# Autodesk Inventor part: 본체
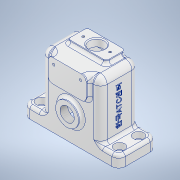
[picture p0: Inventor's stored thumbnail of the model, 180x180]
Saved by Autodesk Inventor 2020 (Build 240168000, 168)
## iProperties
Created: 2023-12
Part Number: 본체
Material: 알루미늄 6061
Document SubType Name: Modeling
Designer: oem
Density: 2.7 g/cm^3
Appearance: 알루미늄 - 평지
Mass: 227.593 g
Surface Area: 373.16 cm^2
Volume: 84.2938 cm^3
Author: oem
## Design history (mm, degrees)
sketch "스케치2"
  geometry: L1 (50, 20)-(-50, 20); L2 (-50, 20)-(-50, -20); L3 (-50, -20)-(50, -20); L4 (50, -20)-(50, 20); L5 (50, 20)-(-50, -20); L6 (-50, 20)-(50, -20); 1 further point
  constraints: 12 end point, 2 midpoint, 2 parallel, 1 horizontal, 1 perpendicular
  dimensions: "d0" = 100 distance of L2.end L3.end; "d1" = 40 distance of L3.end L1.start
extrude "돌출1" new body sketch "스케치2" distance "d2" = 12; taper "d3" = 0 deg
sketch "스케치3"
  geometry: L1 (-31, 72)-(31, 72); L2 (31, 72)-(31, 0); L3 (31, 0)-(-31, 0); L4 (-31, 0)-(-31, 72); L5 (50, 0)-(-50, 0) reference; 2 further points
  constraints: 8 end point, 2 parallel, 1 coincident, 1 horizontal, 1 midpoint, 1 perpendicular
  dimensions: "d4" = 62 distance of L1.start L1.end; "d5" = 72 distance between parallel lines of L5 L1
extrude "돌출2" join sketch "스케치3" stored distance "d6" = 40; taper "d7" = 0 deg
sketch "스케치4"
  geometry: L1 (0, 0)-(100, 0) reference; L2 (81, 72)-(19, 72) reference; L3 (30, 72)-(70, 72); L4 (70, 72)-(70, 48); L5 (70, 48)-(30, 48); L6 (30, 48)-(30, 72); C1 r 12 at (50, 28); 5 further points
  constraints: 8 end point, 3 midpoint, 2 parallel, 2 vertical alignment, 1 centre point, 1 horizontal, 1 perpendicular, 1 point on line
  dimensions: "d8" = 24 diameter of C1; "d9" = 28 distance of point (50, 0) C1.centre; "d10" = 40 distance between parallel lines of L4 L6; "d11" = 24 distance between parallel lines of L5 L2
extrude "돌출3" join sketch "스케치4" distance "d12" = 4; taper "d13" = 0 deg
sketch "스케치5"
  geometry: C1 r 12 at (50, 28) reference; C2 r 20 at (50, 28); 1 further point
  constraints: 1 centre point, 1 coincident
  dimensions: "d14" = 40 diameter of C2
extrude "돌출4" join sketch "스케치5" distance "d15" = 4; taper "d16" = 0 deg
sketch "스케치6"
  geometry: L1 (51, -44)-(11, -44) reference; L2 (11, -3)-(51, -3); L3 (51, -3)-(51, -23); L4 (51, -23)-(11, -23); L5 (11, -23)-(11, -3); L6 (11, -13)-(51, -13); 2 further points
  constraints: 10 end point, 3 midpoint, 2 parallel, 1 horizontal, 1 perpendicular, 1 vertical alignment
  dimensions: "d18" = 20 distance between parallel lines of L4 L2; "d19" = 40 distance of L2.start L2.end; "d20" = 31 distance between parallel lines of L1 L6
extrude "돌출5" join sketch "스케치6" distance "d21" = 4; taper "d22" = 0 deg
sketch "스케치7"
  geometry: C1 r 12 at (0, 0) reference; 2 further points
  constraints: 1 coincident
hole "구멍1" sketch "스케치7" at (0, 0) diameter "d23" = 14.91747; stored, may be unused: countersink angle "d27" = 90 deg, drill point angle "d29" = 0 deg; dims "d24" = 20, "d25" = 4, "d26" = 2, "d28" = 20
sketch "스케치8"
  geometry: L1 (-31, 12)-(-31, 72) reference; L2 (-31, 72)-(31, 72) reference; L3 (31, 72)-(31, 12) reference; L4 (27, 0)-(27, 68); L5 (27, 68)-(-27, 68); L6 (-27, 68)-(-27, 0); L7 (50, 0)-(-50, 0) reference; L8 (-27, 0)-(27, 0); 1 further point
  constraints: 8 end point, 2 point on line, 1 collinear
  dimensions: "d30" = 4 distance between parallel lines of L2 L5
extrude "돌출6" cut sketch "스케치8" stored distance "d31" = 32; taper "d32" = 0 deg
sketch "스케치9"
  geometry: C1 r 20 at (0, 0) reference; C2 r 9 at (0, 0); 1 further point
  constraints: 1 centre point, 1 coincident
  dimensions: "d33" = 18 diameter of C2
extrude "돌출7" cut sketch "스케치9" distance "d34" = 10; taper "d35" = 0 deg
sketch "스케치10"
  geometry: C1 r 9 at (0, 0) reference; C2 r 20 at (0, 0) reference; A1 r 15 centre (0, 0) between (0, 15) and (15, 0); 3 further points
  constraints: 4 point on circle, 2 horizontal alignment, 2 vertical alignment, 1 centre point, 1 coincident
  dimensions: "d36" = 30 diameter of A1
hole "구멍2" sketch "스케치10" at (0, 15), (15, 0), (0, -15), (-15, 0) diameter "d37" = 2.459; stored, may be unused: countersink angle "d41" = 90 deg, drill point angle "d43" = 0 deg; dims "d38" = 10, "d39" = 4, "d40" = 2, "d42" = 10
sketch "스케치11"
  geometry: L1 (70, 72)-(30, 72) reference; L2 (30, 48)-(70, 48) reference; L3 (70, 72)-(30, 72) reference; L4 (50, 72)-(50, 48); 3 further points
  constraints: 2 end point, 2 midpoint, 1 horizontal alignment
  dimensions: "d44" = 28 distance of point (64, 66) point (36, 66); "d45" = 14 distance from line of L4 point (36, 66); "d46" = 6 distance from line of point (36, 66) L1
hole "구멍3" sketch "스케치11" at (36, 66), (64, 66) diameter "d47" = 2.459; stored, may be unused: countersink angle "d51" = 90 deg, drill point angle "d53" = 0 deg; dims "d48" = 10, "d49" = 4, "d50" = 2, "d52" = 10
sketch "스케치12"
  geometry: L1 (51, -3)-(11, -3) reference; C1 r 8 at (31, -13); 1 further point
  constraints: 1 centre point
  dimensions: "d54" = 16 diameter of C1; "d55" = 10 distance from line of C1.centre L1
extrude "돌출8" cut sketch "스케치12" distance "d56" = 20; taper "d57" = 0 deg
sketch "스케치13"
  geometry: C1 r 8 at (31, -13) reference; 3 further points
  constraints: 2 horizontal alignment
  dimensions: "d58" = 28 distance of point (45, -13) point (17, -13); "d59" = 14 distance of C1.centre point (17, -13)
hole "구멍4" sketch "스케치13" at (17, -13), (45, -13) diameter "d60" = 2.459; stored, may be unused: countersink angle "d64" = 90 deg, drill point angle "d66" = 0 deg; dims "d61" = 20, "d62" = 4, "d63" = 2, "d65" = 20
sketch "스케치14"
  geometry: L1 (-41, -10)-(41, -10); L2 (41, -10)-(41, 10); L3 (41, 10)-(-41, 10); L4 (-41, 10)-(-41, -10); L5 (-41, -10)-(41, 10); L6 (41, -10)-(-41, 10); C1 r 5.5 at (-41, 10); C2 r 5.5 at (-41, -10); C3 r 5.5 at (41, 10); C4 r 5.5 at (41, -10); 1 further point
  constraints: 12 end point, 4 centre point, 4 coincident, 2 midpoint, 2 parallel, 1 horizontal, 1 perpendicular
  dimensions: "d67" = 82 distance of L2.end L3.end; "d68" = 20 distance between parallel lines of L1 L3; "d69" = 11 diameter of C1; "d70" = 11 diameter of C2; "d71" = 11 diameter of C3; "d72" = 11 diameter of C4
extrude "돌출9" cut sketch "스케치14" distance "d73" = 6.6; taper "d74" = 0 deg
sketch "스케치17"
  geometry: C1 r 5.5 at (41, -10) reference; C2 r 5.5 at (-41, 10) reference; C3 r 5.5 at (-41, -10) reference; C4 r 3.3 at (-41, 10); C5 r 3.3 at (-41, -10); C6 r 5.5 at (41, 10) reference; C7 r 3.3 at (41, 10); C8 r 3.3 at (41, -10); 1 further point
  constraints: 4 centre point, 4 coincident
  dimensions: "d75" = 6.6 diameter of C4; "d76" = 6.6 diameter of C5; "d77" = 6.6 diameter of C7; "d78" = 6.6 diameter of C8
extrude "돌출10" cut sketch "스케치17" distance "d79" = 20; taper "d80" = 0 deg
fillet "모깎기1" dims "d81" = 7
fillet "모깎기4" dims "d84" = 7
fillet "모깎기14" dims "d94" = 3
fillet "모깎기15" dims "d95" = 3
fillet "모깎기16" dims "d96" = 3
fillet "모깎기17" dims "d97" = 3
chamfer "모따기1" distance "d98" = 1; stored, may be unused: second distance "d99" = 2, angle "d100" = 45 deg
fillet "모깎기18" dims "d101" = 3
fillet "모깎기19" dims "d102" = 3
fillet "모깎기21" dims "d104" = 7
fillet "모깎기22" dims "d105" = 7
fillet "모깎기23" dims "d106" = 5
fillet "모깎기24" dims "d107" = 3
fillet "모깎기25" dims "d108" = 5
fillet "모깎기26" dims "d109" = 3
fillet "모깎기27" dims "d110" = 3
node "작업 평면1"
sketch "스케치18"
  geometry: L1 (0, -20)-(0, -13) reference; L2 (40, 24)-(16, 24) reference; 2 further points
  constraints: 1 other
  dimensions: "d112" = 40 distance from line of L1 point (40, 1); "d116" = 23 distance from line of point (40, 1) L2
feature "엠보싱1" sketch "스케치18" dims "d113" = 0.5, "d114" = 0
node "솔리드1"
feature "A9D066F2-1C7D-4E18-AEED-F7BC21143FA4" dims "d23" = 14.91747, "d24" = 20, "d25" = 4, "d26" = 2, "d27" = 90 deg, "d28" = 20, "d29" = 0
